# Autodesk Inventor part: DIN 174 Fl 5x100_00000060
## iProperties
Created: 2006-03
Part Number: DIN 174 Fl 5x100_00000060
Material: Default
Document SubType Name: Modeling
Designer: Carlo
Stock Number: DIN 174 Fl 5x100
Mass: 773.849 g
Surface Area: 3260.58 cm^2
Volume: 773.849 cm^3
Density: 1 g/cm^3
G_L: 1547.896 mm
G_W: 5.000 mm
G_H: 100.000 mm
AFG_Item: 100 x 5
CSToolsMass: 1.0
CSToolsVolume: 773849.0
CSToolsArea: 3261.0
Author: Carlo
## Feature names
1. AFG_Detailed_DIN 174 Fl 5x100_00000060 [Extrusion]
2. AFG_Simplified_DIN 174 Fl 5x100_00000060 [Extrusion]
3. AFG_StartExtrusion_1 [Extrusion]
4. AFG_StartExtrusion_2 [Extrusion]
5. AFG_EndExtrusion_1 [Extrusion]
6. AFG_EndExtrusion_2 [Extrusion]
